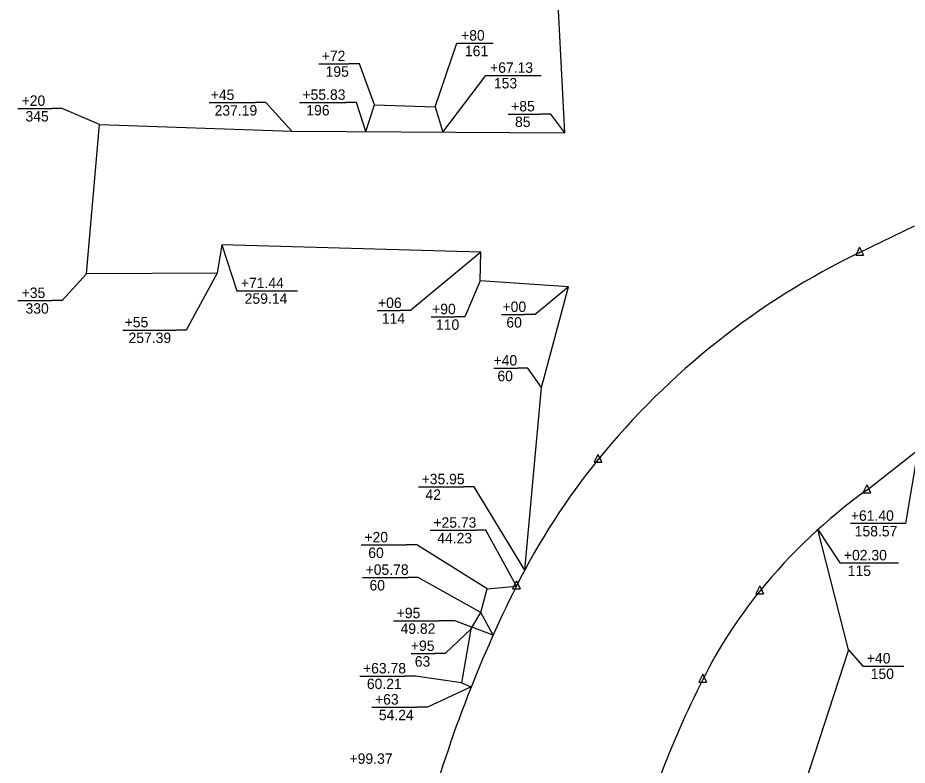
# Model space of a CAD drawing. Extents: x 979729 to 993523, y 1834148 to 1845433.
# Drawn here: x 992343 to 992855, y 1840360 to 1840790 of the extents above; entities that cross this region are included whole.
import ezdxf

# ---------------------------------------------------------------- set-up
doc = ezdxf.new("R2010")
doc.units = 0
for name, color, linetype in [('51', 7, 'Continuous'), ('53', 7, 'Continuous'), ('R_Draft', 7, 'Continuous'), ('S_EXIST_ROW', 7, 'Continuous')]:
    doc.layers.add(name, color=color, linetype=linetype)

msp = doc.modelspace()

# ---------------------------------------------------------------- linework, layer by layer
at = {"layer": '51'}
for p, q in [((992657.88, 1840724.23), (992651.45, 1840844.99)), ((992609.35, 1840655.48), (992460.22, 1840659.83)), ((992609.05, 1840638.99), (992609.35, 1840655.48)), ((992659.93, 1840635.65), (992609.05, 1840638.99)), ((992644.34, 1840577.72), (992659.93, 1840635.65)), ((992634.68, 1840472.56), (992644.34, 1840577.72)), ((992821.13, 1840426.57), (992803.52, 1840495.82)), ((992609.45, 1840448.11), (992613.15, 1840461.84)), ((992613.15, 1840461.84), (992629.87, 1840463.27)), ((992616.48, 1840435.05), (992609.45, 1840448.11)), ((992821.13, 1840426.57), (992762.09, 1840245.7))]:
    msp.add_line(p, q, dxfattribs=at)
msp.add_lwpolyline([(992460.22, 1840659.83), (992457.63, 1840643.5), (992382.32, 1840643.06), (992389.92, 1840729.04), (992500.53, 1840725.16), (992657.88, 1840724.23)], dxfattribs=at)
at = {"layer": '53'}
for p, q in [((992543.12, 1840724.91), (992548.29, 1840740.27)), ((992548.29, 1840740.27), (992583.2, 1840739.16)), ((992583.2, 1840739.16), (992587.58, 1840724.65)), ((992603.75, 1840438.48), (992609.45, 1840448.11)), ((992603.75, 1840438.48), (992598.33, 1840407.61)), ((992598.33, 1840407.61), (992603.89, 1840405.3))]:
    msp.add_line(p, q, dxfattribs=at)
at = {"layer": 'R_Draft'}
for p, q in [((992601.68, 1840775.79), (992616.49, 1840775.79)), ((992516.06, 1840763.96), (992533.48, 1840763.96)), ((992618.35, 1840757.24), (992644.19, 1840757.24)), ((992342.82, 1840738.21), (992362.4, 1840738.21)), ((992452.94, 1840741.61), (992479.67, 1840741.61)), ((992504.94, 1840741.7), (992531.87, 1840741.7)), ((992625.11, 1840735.02), (992643.64, 1840735.02)), ((992474.86, 1840633.31), (992503.85, 1840633.31)), ((992342.82, 1840627.64), (992362.4, 1840627.64)), ((992549.7, 1840621.87), (992562.96, 1840621.87)), ((992580.86, 1840618.32), (992594.13, 1840618.32)), ((992621.39, 1840619.61), (992634.66, 1840619.61)), ((992403.36, 1840610.72), (992433.74, 1840610.72)), ((992616.91, 1840588.76), (992630.54, 1840588.76)), ((992573.56, 1840520.45), (992599.6, 1840520.45)), ((992848.02, 1840499.42), (992822.18, 1840499.42)), ((992580.34, 1840495.43), (992606.38, 1840495.43)), ((992540.6, 1840487.01), (992566.64, 1840487.01)), ((992822.09, 1840476.64), (992849.83, 1840476.64)), ((992541.31, 1840468.31), (992567.35, 1840468.31)), ((992559.2, 1840443.37), (992585.24, 1840443.37)), ((992569.32, 1840424.51), (992582.95, 1840424.51)), ((992835.29, 1840417.34), (992852.91, 1840417.34)), ((992539.81, 1840411.57), (992565.85, 1840411.57)), ((992546.7, 1840393.65), (992572.74, 1840393.65))]:
    msp.add_line(p, q, dxfattribs=at)
for points in [[(992583.2, 1840739.16), (992595.68, 1840775.79), (992601.68, 1840775.79)], [(992548.29, 1840740.27), (992539.48, 1840763.96), (992533.48, 1840763.96)], [(992587.58, 1840724.65), (992612.35, 1840757.24), (992618.35, 1840757.24)], [(992389.92, 1840729.04), (992368.4, 1840738.21), (992362.4, 1840738.21)], [(992500.53, 1840725.16), (992485.67, 1840741.61), (992479.67, 1840741.61)], [(992543.12, 1840724.91), (992537.87, 1840741.7), (992531.87, 1840741.7)], [(992657.88, 1840724.23), (992649.64, 1840735.02), (992643.64, 1840735.02)], [(992460.22, 1840659.83), (992468.86, 1840633.31), (992474.86, 1840633.31)], [(992609.35, 1840655.48), (992568.96, 1840621.87), (992562.96, 1840621.87)], [(992382.32, 1840643.06), (992368.4, 1840627.64), (992362.4, 1840627.64)], [(992457.63, 1840643.5), (992439.74, 1840610.72), (992433.74, 1840610.72)], [(992609.05, 1840638.99), (992600.13, 1840618.32), (992594.13, 1840618.32)], [(992659.93, 1840635.65), (992640.66, 1840619.61), (992634.66, 1840619.61)], [(992644.34, 1840577.72), (992636.54, 1840588.76), (992630.54, 1840588.76)], [(992860.96, 1840541.57), (992854.02, 1840499.42), (992848.02, 1840499.42)], [(992634.68, 1840472.56), (992605.6, 1840520.45), (992599.6, 1840520.45)], [(992629.87, 1840463.27), (992612.38, 1840495.43), (992606.38, 1840495.43)], [(992803.52, 1840495.82), (992816.09, 1840476.64), (992822.09, 1840476.64)], [(992613.15, 1840461.84), (992572.64, 1840487.01), (992566.64, 1840487.01)], [(992609.45, 1840448.11), (992573.35, 1840468.31), (992567.35, 1840468.31)], [(992616.48, 1840435.05), (992594.45, 1840443.37), (992585.24, 1840443.37)], [(992603.75, 1840438.48), (992588.95, 1840424.51), (992582.95, 1840424.51)], [(992821.13, 1840426.57), (992829.29, 1840417.34), (992835.29, 1840417.34)], [(992598.33, 1840407.61), (992571.85, 1840411.57), (992565.85, 1840411.57)], [(992603.89, 1840405.3), (992578.74, 1840393.65), (992572.74, 1840393.65)]]:
    msp.add_lwpolyline(points, dxfattribs=at)
at = {"layer": 'S_EXIST_ROW'}
for p, q in [((992827.51, 1840655.35), (992859.18, 1840670.68)), ((992827.52, 1840658.37), (992825.26, 1840653.84)), ((992827.52, 1840658.37), (992829.75, 1840653.84)), ((992825.26, 1840653.84), (992829.75, 1840653.84)), ((992827.51, 1840655.35), (992827.51, 1840655.35)), ((992831.59, 1840518.58), (992920.92, 1840588.54)), ((992676.88, 1840539.11), (992674.62, 1840534.57)), ((992676.88, 1840539.11), (992679.11, 1840534.57)), ((992674.62, 1840534.57), (992679.11, 1840534.57)), ((992676.87, 1840536.08), (992676.87, 1840536.08)), ((992831.6, 1840521.6), (992829.35, 1840517.06)), ((992831.59, 1840518.58), (992831.59, 1840518.58)), ((992831.6, 1840521.6), (992833.83, 1840517.06)), ((992829.35, 1840517.06), (992833.83, 1840517.06)), ((992629.88, 1840466.3), (992627.62, 1840461.76)), ((992629.88, 1840466.3), (992632.11, 1840461.76)), ((992627.62, 1840461.76), (992632.11, 1840461.76)), ((992629.87, 1840463.27), (992629.87, 1840463.27)), ((992770.01, 1840463.44), (992767.76, 1840458.9)), ((992770.01, 1840463.44), (992772.25, 1840458.9)), ((992767.76, 1840458.9), (992772.25, 1840458.9)), ((992770.01, 1840460.41), (992770.01, 1840460.41)), ((992737.18, 1840412.58), (992734.93, 1840408.04)), ((992737.18, 1840412.58), (992739.41, 1840408.04)), ((992734.93, 1840408.04), (992739.41, 1840408.04)), ((992737.17, 1840409.55), (992737.17, 1840409.55))]:
    msp.add_line(p, q, dxfattribs=at)
for centre, radius in [((992827.51, 1840655.35), 0.0768), ((992827.51, 1840655.35), 0.0384), ((992676.87, 1840536.08), 0.0768), ((992676.87, 1840536.08), 0.0384), ((992831.59, 1840518.58), 0.0768), ((992831.59, 1840518.58), 0.0384), ((992629.87, 1840463.27), 0.0768), ((992629.87, 1840463.27), 0.0384), ((992770.01, 1840460.41), 0.0768), ((992770.01, 1840460.41), 0.0384), ((992737.17, 1840409.55), 0.0768), ((992737.17, 1840409.55), 0.0384)]:
    msp.add_circle(centre, radius, dxfattribs=at)
for centre, radius, start, end in [((993020.31, 1840257.06), 442.5, 115.8302, 140.9087), ((992985.84, 1840285.07), 398.08, 140.9087, 153.4068), ((993020.31, 1840257.06), 322.5, 125.8151, 140.9087), ((993292.86, 1840131.37), 741.43, 153.40682, 164.83346), ((992985.84, 1840285.07), 278.08, 140.9087, 153.4068), ((993292.86, 1840131.37), 621.43, 153.40682, 164.83346)]:
    msp.add_arc(centre, radius, start, end, dxfattribs=at)

# ---------------------------------------------------------------- texts
at = {"layer": 'R_Draft'}
for s, p in [('+80', (992598.05, 1840777.29)), (' 161', (992598.05, 1840768.29)), ('+72', (992517.83, 1840765.46)), ('+67.13', (992614.73, 1840758.74)), (' 195', (992517.83, 1840756.46)), (' 153', (992614.73, 1840749.74)), ('+45', (992453.9, 1840743.11)), ('+55.83', (992506.72, 1840743.2)), ('+20', (992345.03, 1840739.71)), (' 237.19', (992453.9, 1840734.11)), (' 196', (992506.72, 1840734.2)), ('+85', (992626.88, 1840736.52)), (' 345', (992345.03, 1840730.71)), (' 85', (992626.88, 1840727.52)), ('+71.44', (992471.24, 1840634.81)), ('+35', (992345.03, 1840629.14)), (' 259.14', (992471.24, 1840625.81)), (' 330', (992345.03, 1840620.14)), ('+06', (992550.21, 1840623.37)), ('+90', (992581.37, 1840619.82)), ('+00', (992621.9, 1840621.11)), (' 114', (992550.21, 1840614.37)), ('+55', (992404.35, 1840612.22)), (' 110', (992581.37, 1840610.82)), (' 60', (992621.9, 1840612.11)), (' 257.39', (992404.35, 1840603.22)), ('+40', (992616.74, 1840590.26)), (' 60', (992616.74, 1840581.26)), ('+35.95', (992575.33, 1840521.95)), (' 42', (992575.33, 1840512.95)), ('+25.73', (992582.11, 1840496.93)), ('+61.40', (992822.47, 1840500.92)), (' 158.57', (992822.47, 1840491.92)), ('+20', (992542.38, 1840488.51)), (' 44.23', (992582.11, 1840487.93)), (' 60', (992542.38, 1840479.51)), ('+02.30', (992818.46, 1840478.14)), ('+05.78', (992543.08, 1840469.81)), (' 115', (992818.46, 1840469.14)), (' 60', (992543.08, 1840460.81)), ('+95', (992560.97, 1840444.87)), (' 49.82', (992560.97, 1840435.87)), ('+95', (992569.15, 1840426.01)), (' 63', (992569.15, 1840417.01)), ('+40', (992831.67, 1840418.84)), ('+63.78', (992541.58, 1840413.07)), (' 150', (992831.67, 1840409.84)), (' 60.21', (992541.58, 1840404.07)), ('+63', (992548.47, 1840395.15)), (' 54.24', (992548.47, 1840386.15)), ('+99.37', (992533.84, 1840361.05))]:
    msp.add_text(s, height=6, rotation=360, dxfattribs=at).set_placement(p)

doc.saveas('drawing.dxf')
